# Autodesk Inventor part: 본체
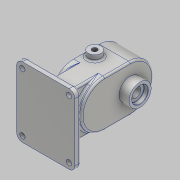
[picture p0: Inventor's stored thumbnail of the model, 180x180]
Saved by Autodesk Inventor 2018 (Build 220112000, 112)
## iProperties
Created: 2020-09
Part Number: 본체
Material: 알루미늄 6061
Document SubType Name: Modeling
Designer: home
Density: 2.7 g/cm^3
Appearance: 알루미늄 - 평지
Mass: 1438.79 g
Surface Area: 787.723 cm^2
Volume: 532.885 cm^3
Author: home
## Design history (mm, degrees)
sketch "스케치1"
  geometry: L1 (50, 60)-(-50, 60); L2 (-50, 60)-(-50, -60); L3 (-50, -60)-(50, -60); L4 (50, -60)-(50, 60); L5 (50, 60)-(-50, -60); 2 further points
  constraints: 10 end point, 2 parallel, 1 coincident, 1 horizontal, 1 midpoint, 1 perpendicular
  dimensions: "d0" = 120 distance of L3.end L1.start; "d1" = 100 distance of L1.start L1.end
extrude "돌출1" new body sketch "스케치1" distance "d3" = 10; taper "d4" = 0 deg
node "작업 평면1"
sketch "스케치3"
  geometry: L1 (120, 0)-(0, 0) reference; L2 (20, 112)-(20, 68); L3 (100, 112)-(100, 68); A1 r 40 centre (60, 112) between (100, 112) and (20, 112); A2 r 40 centre (60, 68) between (20, 68) and (100, 68); 1 further point
  constraints: 4 end point, 4 point on circle, 2 centre point, 2 tangent, 2 vertical alignment, 1 parallel, 1 vertical
  dimensions: "d10" = 80 diameter of A1; "d11" = 80 diameter of A2; "d12" = 44 distance of A2.centre A1.centre; "d13" = 112 distance from line of A1.centre L1
extrude "돌출2" join sketch "스케치3" distance "d14" = 53; taper "d15" = 0 deg
sketch "스케치4"
  geometry: L1 (-84, 112)-(-84, 68); L2 (-36, 112)-(-36, 68); A1 r 40 centre (-60, 112) between (-20, 112) and (-100, 112) reference; A2 r 24 centre (-60, 112) between (-36, 112) and (-84, 112); A3 r 24 centre (-60, 68) between (-84, 68) and (-36, 68); A4 r 40 centre (-60, 68) between (-100, 68) and (-20, 68) reference; 1 further point
  constraints: 4 end point, 4 point on circle, 2 centre point, 2 tangent, 1 coincident, 1 concentric, 1 parallel, 1 vertical
  dimensions: "d16" = 48 diameter of A2; "d17" = 48 diameter of A3
extrude "돌출3" cut sketch "스케치4" distance "d18" = 29; taper "d19" = 0 deg
sketch "스케치5"
  geometry: A1 r 24 centre (-60, 68) between (-84, 68) and (-36, 68) reference; 2 further points
  constraints: 1 vertical alignment
  dimensions: "d20" = 44 distance of point (-60, 112) A1.centre
hole "구멍1" sketch "스케치5" at (-60, 112) diameter "d21" = 17; stored, may be unused: countersink angle "d25" = 90 deg, drill point angle "d27" = 118 deg; dims "d22" = 6, "d23" = 25, "d24" = 15, "d26" = 8
sketch "스케치8"
  geometry: C1 r 12.5 at (-60, 68); A1 r 24 centre (-60, 68) between (-84, 68) and (-36, 68) reference; 1 further point
  constraints: 1 centre point, 1 concentric
  dimensions: "d39" = 25 diameter of C1
extrude "돌출6" cut sketch "스케치8" distance "d40" = 15; taper "d41" = 0 deg
sketch "스케치9"
  geometry: L1 (-83, -68)-(17, -68) reference; L2 (-53, 0)-(-53, 44) reference; C1 r 11 at (-39, 22); 1 further point
  constraints: 1 centre point
  dimensions: "d42" = 22 diameter of C1; "d43" = 90 distance from line of C1.centre L1; "d44" = 14 distance from line of C1.centre L2
extrude "돌출7" join sketch "스케치9" distance "d45" = 10; taper "d46" = 0 deg
fillet "모깎기2" dims "d56" = 3
sketch "스케치11"
  geometry: L1 (53, 44)-(53, 0) reference; L2 (-17, -68)-(83, -68) reference; C1 r 11 at (39, 22); 1 further point
  constraints: 1 centre point
  dimensions: "d57" = 22 diameter of C1; "d58" = 14 distance from line of C1.centre L1; "d59" = 90 distance from line of L2 C1.centre
extrude "돌출8" join sketch "스케치11" distance "d60" = 10; taper "d61" = 0 deg
sketch "스케치12"
  geometry: L1 (14, 22)-(14, -22) reference; L2 (-56, -90)-(44, -90) reference; 2 further points
  dimensions: "d62" = 14 distance from line of L1 point (0, 0); "d63" = 90 distance from line of L2 point (0, 0)
hole "구멍3" sketch "스케치12" at (0, 0) diameter "d64" = 8.917; stored, may be unused: countersink angle "d68" = 90 deg, drill point angle "d70" = 118 deg; dims "d65" = 20, "d66" = 25, "d67" = 15, "d69" = 25.1
fillet "모깎기3" dims "d71" = 3
sketch "스케치13"
  geometry: C1 r 8.5 at (-60, 112) reference; A1 r 31 centre (-60, 112) between (-60, 143) and (-29, 112); 2 further points
  constraints: 3 point on circle, 2 horizontal alignment, 1 centre point, 1 coincident, 1 vertical alignment
  dimensions: "d72" = 62 diameter of A1
hole "구멍4" sketch "스케치13" at (-60, 143), (-91, 112), (-29, 112) diameter "d73" = 4.134; stored, may be unused: countersink angle "d77" = 90 deg, drill point angle "d79" = 118 deg; dims "d74" = 10, "d75" = 25, "d76" = 15, "d78" = 12
node "작업 평면2"
node "작업 평면3"
node "작업 평면4"
sketch "스케치14"
  geometry: L1 (100, 68)-(100, 10); L2 (0, 10)-(120, 10) reference; L3 (20, 68)-(20, 10); L4 (100, 10)-(20, 10); A1 r 40 centre (60, 68) between (20, 68) and (100, 68) reference; A2 r 40 centre (60, 68) between (20, 68) and (100, 68); 2 further points
  constraints: 6 end point, 3 point on circle, 2 point on line, 1 centre point, 1 coincident, 1 collinear, 1 parallel, 1 tangent, 1 vertical
extrude "돌출9" join sketch "스케치14" distance "d86" = 37; taper "d87" = 0 deg
fillet "모깎기4" dims "d88" = 3
fillet "모깎기5" dims "d89" = 10
sketch "스케치15"
  geometry: A1 r 10 centre (-40, 50) between (-40, 60) and (-50, 50) reference; A2 r 10 centre (40, 50) between (50, 50) and (40, 60) reference; A3 r 10 centre (40, -50) between (40, -60) and (50, -50) reference; A4 r 10 centre (-40, -50) between (-50, -50) and (-40, -60) reference; 1 further point
hole "구멍5" sketch "스케치15" at (-40, 50), (40, 50), (40, -50), (-40, -50) diameter "d90" = 9; stored, may be unused: countersink angle "d94" = 90 deg, drill point angle "d96" = 118 deg; dims "d91" = 10, "d92" = 25, "d93" = 15, "d95" = 12
fillet "모깎기6" dims "d97" = 3
fillet "모깎기7" dims "d98" = 3
fillet "모깎기8" dims "d99" = 3
chamfer "모따기2" distance "d100" = 1; stored, may be unused: second distance "d101" = 2, angle "d102" = 30 deg
sketch "스케치17"
  geometry: L1 (40, 60)-(-40, 60) reference; L2 (-50, 50)-(-50, -50) reference; 2 further points
  constraints: 1 other
  dimensions: "d103" = 60 distance from line of L1 point (-38, 0); "d104" = 12 distance from line of point (-38, 0) L2
feature "엠보싱1" sketch "스케치17" dims "d0" = 120, "d1" = 100, "d105" = 0.5, "d106" = 0
sketch "스케치18"
  geometry: C1 r 8.5 at (60, 112) reference; C2 r 19 at (60, 112); 1 further point
  constraints: 1 centre point, 1 coincident
  dimensions: "d116" = 38 diameter of C2
extrude "돌출10" join sketch "스케치18" distance "d117" = 17; taper "d118" = 0 deg
sketch "스케치19"
  geometry: C1 r 14 at (0, 0); C2 r 19 at (0, 0) reference; 1 further point
  constraints: 1 centre point, 1 concentric
  dimensions: "d119" = 28 diameter of C1
extrude "돌출11" cut sketch "스케치19" distance "d120" = 7.3; taper "d121" = 0 deg
chamfer "모따기6" distance "d122" = 0.7; stored, may be unused: second distance "d123" = 2, angle "d124" = 30 deg
fillet "모깎기9" dims "d125" = 0.5
node "솔리드1"
mirror "미러1"
other parameters: "d9" = -17, "d81" = -25
